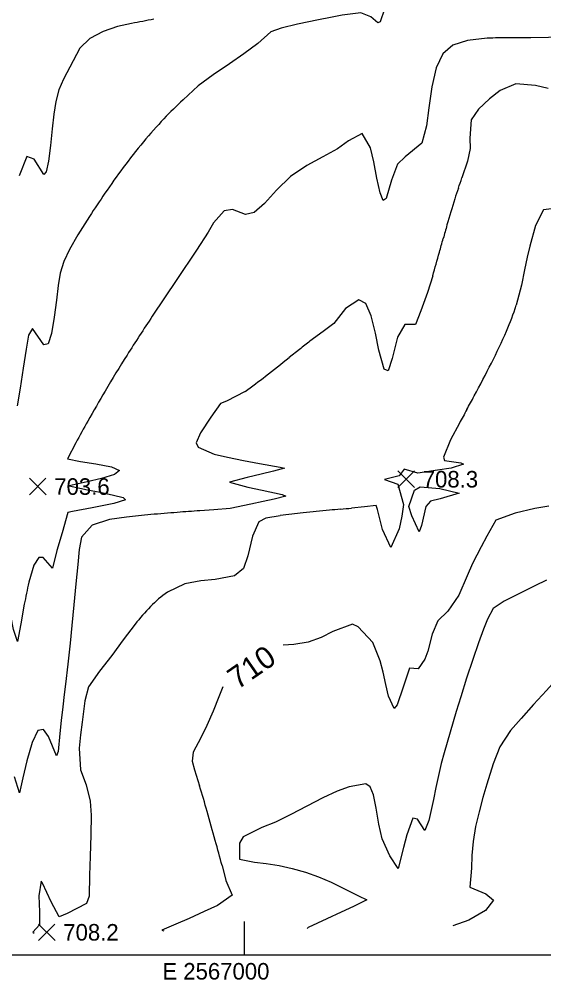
# Model space of a CAD drawing. Extents: x 2566079 to 2571326, y 424054 to 426896.
# Drawn here: x 2566796 to 2567271, y 424054 to 424925 of the extents above; entities that cross this region are included whole.
import ezdxf

# ---------------------------------------------------------------- set-up
doc = ezdxf.new("R2010")
doc.units = 0
for name, color, linetype in [('Contour_ADS_Label_Major', 7, 'Continuous'), ('Contour_ADS_Major', 7, 'Continuous'), ('Contour_ADS_Minor', 7, 'Continuous'), ('Contour_ADS_Spot_Elevation', 7, 'Continuous'), ('Contour_ADS_State_Plane_Border', 7, 'Continuous')]:
    doc.layers.add(name, color=color, linetype=linetype)

# ---------------------------------------------------------------- blocks, each defined once
blk = doc.blocks.new('S750')
at = {"layer": 'Contour_ADS_Spot_Elevation'}
for p, q in [((-0.5, 0.498), (0.5, -0.498)), ((-0.498, -0.5), (0.498, 0.5))]:
    blk.add_line(p, q, dxfattribs=at)

msp = doc.modelspace()

# ---------------------------------------------------------------- linework, layer by layer
at = {"layer": 'Contour_ADS_Major'}
for points in [[(2566897.71, 424921.12), (2566884.81, 424918.33), (2566871.9, 424913.99), (2566859.77, 424907.42), (2566850.69, 424898.87), (2566844.59, 424887.39), (2566835.84, 424870.66), (2566831.82, 424860.89), (2566829.03, 424850.52), (2566827.17, 424839.02), (2566825.68, 424825.68), (2566824.09, 424810.52), (2566822.28, 424796.38), (2566820.25, 424786.84), (2566817.98, 424784.4), (2566809.49, 424798.33), (2566802.65, 424800.73), (2566795.78, 424783.23)], [(2567275.76, 424483.56), (2567263.27, 424481.62), (2567245.47, 424477.48), (2567227.8, 424470.88), (2567219.67, 424456.53), (2567214.58, 424446.9), (2567206.77, 424431.77), (2567201.85, 424420.61), (2567194.26, 424402.92), (2567184.26, 424388.63), (2567175.18, 424379.85), (2567170.22, 424367.75), (2567166.09, 424352.37), (2567163.49, 424345.05), (2567157.52, 424336.39), (2567149.63, 424336.85), (2567143.92, 424319.75), (2567138.45, 424303.57), (2567135.57, 424300.33), (2567130.47, 424311.46), (2567128.1, 424322.03), (2567125.7, 424333.07), (2567123.05, 424343.57), (2567116.25, 424360.09), (2567103.16, 424374.29), (2567097.87, 424376.71), (2567079.95, 424370.13), (2567069.55, 424364.7), (2567057.59, 424360.36), (2567044.69, 424358.43), (2567035.12, 424357.83)], [(2566980.35, 424319.82), (2566976.76, 424310.75), (2566971.49, 424298), (2566965.73, 424284.94), (2566960.36, 424273.72), (2566953.35, 424260.71), (2566952.44, 424252.57), (2566954.77, 424244.84), (2566959.34, 424230.21)], [(2566979.71, 424157.87), (2566983.21, 424144.32), (2566988.7, 424131.13), (2566975.54, 424121.81), (2566963.56, 424116.17), (2566949.79, 424110.06), (2566937.86, 424104.9), (2566925.18, 424099.34), (2566926.81, 424098.67)]]:
    msp.add_lwpolyline(points, dxfattribs=at)
for centre, radius, start, end in [((2567316.28, 422834.74), 2127.95, 100.79282, 101.344), ((2565283.78, 423728.88), 1748.95, 15.86513, 16.65718), ((2564180, 423410.67), 2897.68, 15.40736, 15.95098), ((2564649.19, 423535.47), 2412.19, 14.95267, 15.5105)]:
    msp.add_arc(centre, radius, start, end, dxfattribs=at)
at = {"layer": 'Contour_ADS_Minor'}
msp.add_line((2567049.96, 424625.79), (2567040.56, 424618.39), dxfattribs=at)
for points in [[(2567135.59, 424955.58), (2567121.03, 424955.31), (2567101.89, 424951.58), (2567098.74, 424950.18), (2567115.43, 424945.39), (2567123.01, 424942.33), (2567126.82, 424934.16), (2567123.13, 424922.75), (2567120.87, 424921.67), (2567114.66, 424927.34), (2567105.41, 424930.73), (2567088.41, 424928.68), (2567077.97, 424926.62), (2567067.09, 424924.45), (2567048.2, 424920.68), (2567033.27, 424916.95), (2567023.81, 424913.57), (2567012.1, 424903.18), (2566999.26, 424893.79), (2566986.41, 424884.54), (2566971.69, 424874.69), (2566958.06, 424864.54), (2566944.29, 424852.07)], [(2567219.96, 424907.8), (2567202.04, 424905.85), (2567188.81, 424901.48), (2567179.83, 424893.6), (2567173.9, 424881.07), (2567169.94, 424863.67), (2567167.21, 424844.75), (2567165.04, 424828.54), (2567160.61, 424812.68), (2567145.57, 424800.26), (2567138.69, 424793.63), (2567133.32, 424779.02), (2567128.5, 424762.43), (2567125.74, 424760.68), (2567122.94, 424767.79), (2567120.11, 424780.91), (2567117.24, 424795.74), (2567114.26, 424808.49), (2567106.77, 424821.56), (2567094.22, 424814.76), (2567084.23, 424807.66), (2567071.13, 424800.43), (2567056.37, 424792.41), (2567041.83, 424782.4), (2567029.05, 424770.01), (2567018.15, 424757.97), (2567008.89, 424749.83), (2567001.06, 424747.96), (2566989.17, 424752.59), (2566981.53, 424751.44), (2566971.78, 424740.48), (2566966.99, 424732.16), (2566956.53, 424715.74), (2566938.72, 424689.16), (2566916.41, 424655.86)], [(2567322.21, 424912.14), (2567303.62, 424910.69), (2567287.76, 424909.07), (2567275.59, 424908.55), (2567259.58, 424908.29), (2567240.18, 424908.3)], [(2567275.23, 424862.16), (2567263.83, 424864.88), (2567245.9, 424866.61), (2567231.72, 424860.46), (2567222, 424852.88), (2567212.26, 424843.45), (2567205.43, 424833.9), (2567204.24, 424817.22), (2567204.6, 424807.95), (2567202.12, 424796.35), (2567197.11, 424781.4)], [(2567283.05, 424753.75), (2567271.14, 424752.24), (2567263.66, 424738.13), (2567258.51, 424719.4), (2567256.13, 424709.49), (2567253.77, 424698.02), (2567251.06, 424683.93), (2567246.33, 424665.87)], [(2566859.54, 424746.34), (2566848.9, 424729.65), (2566841.3, 424716.44), (2566836.2, 424705.31), (2566833.03, 424694.86), (2566831.05, 424683.72), (2566829.47, 424670.52), (2566827.61, 424654.85), (2566825.19, 424640.14), (2566822.01, 424630.79), (2566818.05, 424629.77), (2566807.86, 424644.78), (2566804.3, 424638.69), (2566802.05, 424625.88), (2566799.42, 424608.76), (2566796.68, 424590.65), (2566794.04, 424574.7)], [(2567170.69, 424692.45), (2567166.01, 424677.33), (2567159.85, 424660.7), (2567154.97, 424648.34), (2567145.3, 424648.24), (2567138.74, 424636.95), (2567133.91, 424617.67), (2567130.26, 424606.4), (2567126.52, 424607.73), (2567121.68, 424625.02), (2567118.61, 424640.35), (2567114.78, 424656.11), (2567109.88, 424667.43), (2567103.8, 424670.82), (2567091.55, 424662.81), (2567080.93, 424649.31), (2567071.25, 424642.06), (2567059.36, 424633.2)], [(2567000.58, 424587.7), (2566983.64, 424578.79), (2566978.2, 424576.88), (2566969.38, 424564.31), (2566960.09, 424550.07), (2566956.32, 424540.97), (2566958.09, 424537.18), (2566972.6, 424530.96), (2566984.75, 424528.08), (2566999.21, 424525.12), (2567013.65, 424522.36), (2567032.4, 424518.96), (2567036.31, 424518.11), (2567026.2, 424515.43), (2567015.18, 424512.71), (2567002.56, 424509.58), (2566986.33, 424505.41), (2567003.07, 424500.86), (2567016.04, 424498.19), (2567034.11, 424494.22), (2567037.33, 424492.81), (2567026.81, 424490.09), (2567016.92, 424487.9), (2567005.68, 424485.43), (2566987.05, 424481.58), (2566972.3, 424480.41), (2566959.65, 424479.54)], [(2567194.81, 424558.84), (2567186.73, 424543.67), (2567180.35, 424528.02), (2567181.42, 424525.22), (2567196.19, 424522.87), (2567198.65, 424521.72), (2567187.3, 424518.24), (2567175.01, 424516.27), (2567157.14, 424513.74), (2567144.75, 424517.35), (2567140.32, 424511.07), (2567126.94, 424507.78), (2567139.05, 424503.63), (2567144.11, 424485.06), (2567142.65, 424474.73), (2567140.15, 424463.18), (2567132.74, 424446.34), (2567125.08, 424462.56), (2567120.67, 424480.67), (2567119.23, 424484.29), (2567108.68, 424483.04), (2567097.14, 424481.91)], [(2566847.1, 424541.06), (2566839.44, 424526.51), (2566851.36, 424524.19), (2566865.24, 424522.14), (2566879.37, 424519.31), (2566886.64, 424515.92), (2566882.23, 424512.25), (2566870.36, 424508.74), (2566857.5, 424505.87), (2566840.97, 424502.11), (2566857.71, 424498.62), (2566869.28, 424496.37), (2566881.3, 424493.8), (2566889.89, 424491.41), (2566892.12, 424489.53), (2566881.44, 424486.23), (2566862.02, 424482.11), (2566844.09, 424478.87), (2566839.83, 424477.82), (2566834.6, 424459.47), (2566829.78, 424443.57), (2566826.1, 424427.45), (2566817.48, 424437.07), (2566813.47, 424437.14), (2566809.06, 424430.3), (2566804.55, 424414.65)], [(2566800.42, 424394.79), (2566797.18, 424376.98), (2566794.12, 424361.11), (2566790.57, 424371.96), (2566788.1, 424384.26), (2566785.16, 424399.63), (2566782.32, 424415.86), (2566780.05, 424431.03), (2566778.32, 424444.43), (2566775.67, 424464.23), (2566766.95, 424473.93), (2566756.73, 424475.34), (2566743.65, 424475.26), (2566729.76, 424474.56), (2566716.33, 424473.96), (2566701.6, 424473.7), (2566683.05, 424473.88)], [(2566893.02, 424473.81), (2566877.56, 424471.52), (2566861.94, 424466.37), (2566852.39, 424455.69), (2566850.28, 424444.35), (2566848.79, 424430.93), (2566847.02, 424413.41), (2566845.16, 424394.2), (2566843.4, 424375.62), (2566841.87, 424359.48), (2566839.94, 424340.59), (2566837.76, 424322.29), (2566836.69, 424313.09), (2566835.3, 424301.68), (2566833.82, 424289.37), (2566832.53, 424277.76), (2566830.97, 424261.45), (2566829.51, 424257.42), (2566822.3, 424275), (2566817.86, 424281.31), (2566812.82, 424280.46), (2566807.58, 424269.34), (2566802.79, 424252.71), (2566799.11, 424237.31), (2566795.92, 424223.93), (2566791.45, 424238.32)], [(2567032.37, 424475.07), (2567019.46, 424472.69), (2567012.97, 424469.5), (2567007.23, 424456.41), (2567002.95, 424438.55), (2566999.2, 424427.08), (2566990.81, 424420.63), (2566973.31, 424417.07), (2566960.55, 424416.04), (2566945.86, 424413.17), (2566930.21, 424405.85)], [(2567273.64, 424416.69), (2567263.2, 424411.36), (2567252.9, 424406.39), (2567235.32, 424397.6), (2567225.38, 424390.88), (2567220.3, 424381.17), (2567216.78, 424372.1), (2567212.26, 424359.89), (2567207.02, 424344.83), (2567201.4, 424327.68), (2567196.11, 424310.91), (2567191.95, 424297.42), (2567186.3, 424278.88), (2567180.89, 424260.01), (2567178.36, 424250.29), (2567175.8, 424239.63), (2567173.42, 424228.62), (2567171.22, 424217.78), (2567167.25, 424198.69), (2567163.35, 424189.56), (2567156.88, 424199.94), (2567152.73, 424200.77), (2567147.27, 424185.7), (2567144.24, 424174.22), (2567139.21, 424155.15), (2567131.85, 424166.7), (2567124.74, 424182.22), (2567121.85, 424195.51), (2567119.36, 424209.99), (2567116.9, 424222.18), (2567114, 424229.38), (2567109.91, 424232.14), (2567095.04, 424229.41), (2567083.92, 424225.27), (2567070.92, 424219.35), (2567056.61, 424211.9), (2567041.95, 424204.07), (2567027.97, 424197.26), (2567015.66, 424192.39), (2566998.92, 424184.06), (2566995.53, 424178.19), (2566995.33, 424163.69)], [(2566900.78, 424376.7), (2566890.04, 424362.59), (2566879.68, 424348.26), (2566868.68, 424334.06), (2566858.5, 424319.85), (2566855.13, 424307.24), (2566852.75, 424287.96), (2566851.25, 424276.3), (2566850.06, 424264.43), (2566851.42, 424244.7), (2566856.6, 424231.02), (2566860.25, 424216.32), (2566860.9, 424203.71), (2566860.72, 424185.73), (2566860.08, 424166), (2566859.46, 424149.29), (2566859.29, 424130.18), (2566856.68, 424123.62), (2566839.17, 424114.33), (2566832.02, 424111.39), (2566824.89, 424124.93), (2566816.84, 424142.05), (2566815.84, 424143.82), (2566813.71, 424130.37), (2566814.32, 424116.14), (2566814.23, 424104.24), (2566808.25, 424097.44), (2566809.42, 424096.53)], [(2567333.96, 424372.32), (2567321.76, 424362.35), (2567306.32, 424350.68), (2567292.79, 424337.47), (2567284.15, 424327.95), (2567273.75, 424316.5), (2567262.1, 424303.86), (2567250.71, 424291.29), (2567241.28, 424280.21), (2567231.54, 424265.56), (2567225.29, 424250.07), (2567219.66, 424231.59), (2567216.16, 424219.49), (2567212.61, 424206.57), (2567209.47, 424193.26), (2567207.21, 424179.88), (2567206.14, 424166.91), (2567205.8, 424155.46), (2567204.16, 424138.49), (2567218.68, 424132.21), (2567225.64, 424126.45), (2567218.59, 424117.08), (2567203.27, 424108.56), (2567188.77, 424103.43)], [(2566995.33, 424163.69), (2567009.13, 424160.96), (2567019.55, 424159.76), (2567031.32, 424157.94), (2567043.34, 424155.34), (2567055.3, 424151.93), (2567067.07, 424147.69), (2567078.43, 424142.75), (2567088.73, 424137.75), (2567103.36, 424130.47), (2567110.85, 424126.86), (2567098.83, 424120.8), (2567087.51, 424115.62), (2567074.6, 424109.71), (2567057.77, 424101.89), (2567056.81, 424101.03)]]:
    msp.add_lwpolyline(points, dxfattribs=at)
msp.add_lwpolyline([(2567177.36, 424490.21), (2567168.55, 424488.23), (2567164.5, 424483.24), (2567160.55, 424466.12), (2567158.48, 424460.34), (2567151.73, 424474.87), (2567148.83, 424483.28), (2567154.06, 424498.32), (2567159.28, 424501.32), (2567177.13, 424499.61), (2567194.75, 424495.4), (2567177.36, 424490.21)], close=True, dxfattribs=at)
for centre, radius, start, end in [((2567242.78, 424394.17), 514.14, 90.28943, 92.54361), ((2567253.32, 424525.41), 449.68, 133.41155, 136.52206), ((2567256.25, 424522.02), 454.13, 136.46548, 140.00631), ((2567320.82, 424472.15), 535.66, 140.35888, 143.52049), ((2567512.64, 424330.56), 774.08, 143.53508, 145.65473), ((2561428.1, 426725.03), 6087.63, 341.2853, 341.380869), ((2567693.77, 424204.52), 994.74, 145.54694, 146.99719), ((2567780.24, 424568.32), 620.68, 160.86441, 161.80176), ((2568141.22, 424465.85), 995.72, 162.68768, 164.10539), ((2568503.17, 424364.52), 1371.58, 164.1752, 164.70943), ((2554698.67, 428191.72), 12953.64, 344.426017, 344.482625), ((2560610.06, 426545.28), 6817.25, 344.229461, 344.416703), ((2566983.2, 424750.7), 276.46, 336.94325, 342.13221), ((2568680.65, 423486.47), 2116.6, 146.46241, 147.59754), ((2566709.29, 424874.61), 577.07, 333.08616, 336.27412), ((2567512.29, 424048.97), 739.23, 127.78477, 128.7125), ((2568087.64, 423870.08), 1410.38, 147.84597, 149.39866), ((2542322.22, 456013.45), 39958.05, 308.175308, 308.2145), ((2565929.23, 425272.04), 1452.53, 331.70578, 333.03526), ((2566679.11, 425038.28), 553.5, 305.5067, 307.89539), ((2568112.82, 423856.21), 1439.11, 149.43349, 150.68917), ((2565371.44, 425572.02), 2085.87, 331.32675, 331.71269), ((2569857.51, 423120.14), 3026.52, 151.35085, 151.61693), ((2567938.45, 423951.59), 1240.37, 150.58785, 151.62512), ((2567172.36, 421447.19), 3039.8, 94.01258, 94.40058), ((2567321.24, 421960.79), 2531, 95.53768, 96.07901), ((2567438.12, 420745.3), 3752.1, 95.36847, 95.52294), ((2566383.04, 431842.54), 7395.18, 275.462892, 275.541272), ((2566987.23, 423654.32), 824.89, 95.02292, 96.55819), ((2567084, 422575.63), 1907.9, 94.35515, 95.08166), ((2567136.42, 423692.66), 789.3, 96.05171, 97.57529), ((2567294.8, 424302.34), 502.95, 167.09695, 169.40795), ((2566991.35, 424318.52), 106.61, 124.99667, 135.98056), ((2567067.94, 424244.49), 213.13, 135.97835, 141.66001)]:
    msp.add_arc(centre, radius, start, end, dxfattribs=at)
at = {"layer": 'Contour_ADS_State_Plane_Border'}
msp.add_line((2567000, 424077.11), (2567000, 424107.11), dxfattribs=at)
msp.add_lwpolyline([(2566079.33, 424077.11), (2571302.93, 424077.11), (2571302.93, 426873.74), (2566079.33, 426873.74), (2566079.33, 424077.11)], close=True, dxfattribs=at)

# ---------------------------------------------------------------- block references
at = {"layer": 'Contour_ADS_Spot_Elevation', "xscale": 15, "yscale": 15}
for p in [(2567146.58, 424508.1), (2566812.58, 424501.46), (2566820.74, 424097.43)]:
    msp.add_blockref('S750', p, dxfattribs=at)

# ---------------------------------------------------------------- texts
at = {"layer": 'Contour_ADS_Label_Major'}
msp.add_text('710', height=20, rotation=34.761, dxfattribs=at).set_placement((2566993.67, 424316.89))
at = {"layer": 'Contour_ADS_Spot_Elevation'}
for s, p in [('708.3', (2567161.58, 424500.6)), ('703.6', (2566827.58, 424493.96)), ('708.2', (2566835.74, 424089.93))]:
    msp.add_text(s, height=15, dxfattribs=at).set_placement(p)
at = {"layer": 'Contour_ADS_State_Plane_Border'}
msp.add_text(' E 2567000', height=15, dxfattribs=at).set_placement((2566920, 424054.61))

doc.saveas('drawing.dxf')
